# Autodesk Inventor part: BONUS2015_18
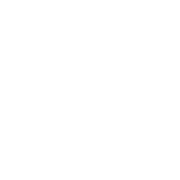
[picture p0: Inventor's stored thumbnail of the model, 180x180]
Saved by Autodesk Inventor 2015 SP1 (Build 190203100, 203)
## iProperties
Created: 2015-05
Part Number: BONUS2015_18
Material: Generisch
Document SubType Name: Modeling
Density: 1 g/cm^3
Appearance: Vorgabe
xx: 18
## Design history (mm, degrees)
